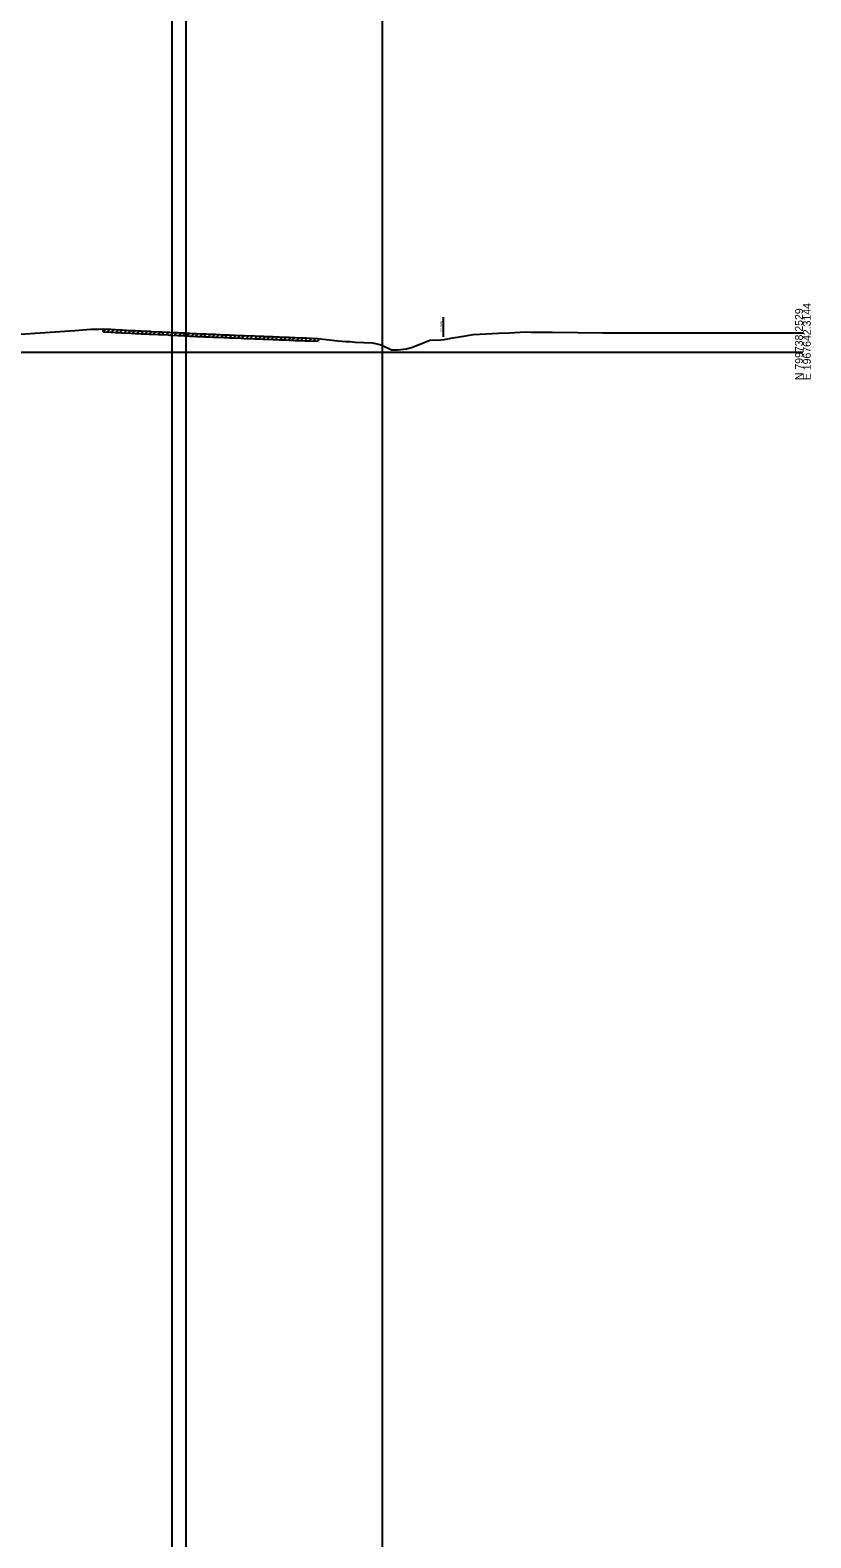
# Model space of a CAD drawing. Extents: x -119 to 6018, y -82 to 34226.
# Drawn here: x 324 to 603, y 32076 to 32614 of the extents above; entities that cross this region are included whole.
import ezdxf

# ---------------------------------------------------------------- set-up
doc = ezdxf.new("R2010")
doc.units = 0
for name, color, linetype in [('RD_GPK_XS_Cell', 7, 'Continuous'), ('RD_Sketch1', 7, 'Continuous'), ('RD_XS_ExGround', 7, 'Continuous'), ('RD_XS_ExPaveRet', 7, 'Continuous'), ('RD_XS_ExRW', 7, 'Continuous')]:
    doc.layers.add(name, color=color, linetype=linetype)

msp = doc.modelspace()

# ---------------------------------------------------------------- linework, layer by layer
at = {"layer": 'RD_GPK_XS_Cell'}
msp.add_line((300, 32499), (600, 32499), dxfattribs=at)
at = {"layer": 'RD_Sketch1'}
for p, q in [((375, -82), (375, 34226.15)), ((380, -82), (380, 34226.15)), ((450, -82), (450, 34226.15))]:
    msp.add_line(p, q, dxfattribs=at)
at = {"layer": 'RD_XS_ExGround'}
msp.add_lwpolyline([(319.1, 32505.25), (340.25, 32506.72), (345.99, 32507.12), (346.32, 32507.13), (348.98, 32507.22), (350.35, 32507.26), (353.15, 32507.14), (354.76, 32507.04), (356.69, 32506.93), (357.06, 32506.91), (360.22, 32506.74), (361.85, 32506.66), (363.39, 32506.58), (363.89, 32506.55), (365.38, 32506.48), (366.78, 32506.42), (367.16, 32506.4), (367.57, 32506.38), (370.17, 32506.27), (370.7, 32506.25), (371.27, 32506.22), (373.56, 32506.12), (374.23, 32506.08), (374.96, 32506.04), (376.97, 32505.94), (378.64, 32505.86), (379.52, 32505.81), (380.35, 32505.77), (381.31, 32505.73), (382.34, 32505.68), (383.73, 32505.61), (386.02, 32505.51), (386.59, 32505.49), (387.11, 32505.46), (388.36, 32505.41), (389.71, 32505.36), (390.51, 32505.33), (393.4, 32505.2), (393.92, 32505.18), (395.44, 32505.11), (397.31, 32505.04), (399.61, 32504.94), (400.79, 32504.89), (404.48, 32504.75), (406.07, 32504.69), (407.53, 32504.64), (408.15, 32504.61), (410.87, 32504.51), (411.85, 32504.46), (413.13, 32504.41), (414.34, 32504.36), (414.92, 32504.34), (415.55, 32504.32), (416.7, 32504.27), (417.74, 32504.23), (418.85, 32504.19), (420.86, 32504.13), (421.42, 32504.11), (422.3, 32504.07), (422.94, 32504.04), (423.63, 32504.01), (424.53, 32503.98), (427.04, 32503.88), (427.14, 32503.9), (428.97, 32503.66), (434.15, 32503.03), (437, 32502.82), (437.77, 32502.77), (438.38, 32502.72), (440.29, 32502.58), (446.46, 32502.28), (449.51, 32501.55), (453.21, 32499.82), (455.35, 32499.75), (458.65, 32500.12), (460.73, 32500.79), (466.87, 32503.3), (470.86, 32503.31), (472.01, 32503.51), (472.65, 32503.62), (473.97, 32503.85), (475.03, 32504.04), (477.54, 32504.47), (478.24, 32504.6), (478.99, 32504.73), (480.97, 32505.07), (482.4, 32505.32), (491.45, 32505.74), (495.38, 32505.92), (501.08, 32506.17), (503.09, 32506.15), (508.44, 32506.13), (510.65, 32506.07), (528.62, 32505.85), (544.18, 32505.92), (600, 32505.84)], dxfattribs=at)
at = {"layer": 'RD_XS_ExPaveRet'}
for p, q in [((350.35, 32506.26), (350.35, 32507.26)), ((350.35, 32506.26), (351.31, 32507.22)), ((350.35, 32506.26), (353.15, 32506.14)), ((351.85, 32506.2), (352.81, 32507.15)), ((353.15, 32506.14), (354.76, 32506.04)), ((353.35, 32506.12), (354.3, 32507.06)), ((354.76, 32506.04), (356.69, 32505.93)), ((354.85, 32506.03), (355.8, 32506.98)), ((356.35, 32505.95), (357.3, 32506.9)), ((356.69, 32505.93), (357.06, 32505.91)), ((357.06, 32505.91), (360.22, 32505.74)), ((357.85, 32505.87), (358.8, 32506.81)), ((359.35, 32505.78), (360.3, 32506.73)), ((360.85, 32505.7), (361.81, 32506.66)), ((362.35, 32505.63), (363.31, 32506.58)), ((363.85, 32505.56), (364.81, 32506.51)), ((365.35, 32505.48), (366.31, 32506.44)), ((366.85, 32505.41), (367.81, 32506.37)), ((368.35, 32505.35), (369.31, 32506.31)), ((369.85, 32505.29), (370.81, 32506.24)), ((371.35, 32505.22), (372.31, 32506.17)), ((372.85, 32505.15), (373.81, 32506.1)), ((374.35, 32505.07), (375.31, 32506.03)), ((375.85, 32505), (376.81, 32505.95)), ((377.35, 32504.92), (378.31, 32505.87)), ((378.85, 32504.85), (379.81, 32505.8)), ((360.22, 32505.74), (361.85, 32505.66)), ((361.85, 32505.66), (363.39, 32505.58)), ((363.39, 32505.58), (363.89, 32505.55)), ((363.89, 32505.55), (365.38, 32505.48)), ((365.38, 32505.48), (366.78, 32505.42)), ((366.78, 32505.42), (367.16, 32505.4)), ((367.16, 32505.4), (367.57, 32505.38)), ((367.57, 32505.38), (370.17, 32505.27)), ((370.17, 32505.27), (370.7, 32505.25)), ((370.7, 32505.25), (371.27, 32505.22)), ((371.27, 32505.22), (373.56, 32505.12)), ((373.56, 32505.12), (374.23, 32505.08)), ((374.23, 32505.08), (374.96, 32505.04)), ((374.96, 32505.04), (376.97, 32504.94)), ((376.97, 32504.94), (378.64, 32504.86)), ((378.64, 32504.86), (379.52, 32504.81)), ((379.52, 32504.81), (380.35, 32504.77)), ((380.35, 32504.77), (381.31, 32505.73)), ((380.35, 32504.77), (381.31, 32504.73)), ((381.31, 32504.73), (382.34, 32504.68)), ((381.85, 32504.7), (382.81, 32505.66)), ((382.34, 32504.68), (383.73, 32504.61)), ((383.35, 32504.63), (384.31, 32505.59)), ((383.73, 32504.61), (386.02, 32504.51)), ((384.85, 32504.56), (385.81, 32505.52)), ((386.02, 32504.51), (386.59, 32504.49)), ((386.35, 32504.5), (387.31, 32505.45)), ((386.59, 32504.49), (387.11, 32504.46)), ((387.11, 32504.46), (388.36, 32504.41)), ((387.85, 32504.43), (388.82, 32505.4)), ((388.36, 32504.41), (389.71, 32504.36)), ((389.35, 32504.38), (390.32, 32505.34)), ((389.71, 32504.36), (390.51, 32504.33)), ((390.51, 32504.33), (393.4, 32504.2)), ((390.85, 32504.32), (391.81, 32505.27)), ((392.35, 32504.25), (393.31, 32505.21)), ((393.4, 32504.2), (393.92, 32504.18)), ((393.85, 32504.18), (394.81, 32505.14)), ((393.92, 32504.18), (395.44, 32504.11)), ((395.35, 32504.12), (396.31, 32505.08)), ((395.44, 32504.11), (397.31, 32504.04)), ((396.85, 32504.06), (397.81, 32505.01)), ((397.31, 32504.04), (399.61, 32503.94)), ((398.35, 32503.99), (399.31, 32504.95)), ((399.61, 32503.94), (400.79, 32503.89)), ((399.85, 32503.93), (400.81, 32504.89)), ((400.79, 32503.89), (404.48, 32503.75)), ((401.35, 32503.87), (402.32, 32504.83)), ((402.85, 32503.81), (403.82, 32504.77)), ((404.35, 32503.75), (405.32, 32504.72)), ((404.48, 32503.75), (406.07, 32503.69)), ((405.85, 32503.7), (406.82, 32504.66)), ((406.07, 32503.69), (407.53, 32503.64)), ((407.35, 32503.64), (408.32, 32504.61)), ((407.53, 32503.64), (408.15, 32503.61)), ((408.15, 32503.61), (410.87, 32503.51)), ((408.85, 32503.59), (409.82, 32504.55)), ((410.35, 32503.53), (411.32, 32504.49)), ((410.87, 32503.51), (411.85, 32503.46)), ((411.85, 32503.46), (412.81, 32504.42)), ((411.85, 32503.46), (413.13, 32503.41)), ((413.13, 32503.41), (414.34, 32503.36)), ((413.35, 32503.4), (414.32, 32504.36)), ((414.34, 32503.36), (414.92, 32503.34)), ((414.85, 32503.34), (415.82, 32504.3)), ((414.92, 32503.34), (415.55, 32503.32)), ((415.55, 32503.32), (416.7, 32503.27)), ((416.35, 32503.28), (417.32, 32504.24)), ((416.7, 32503.27), (417.74, 32503.23)), ((417.74, 32503.23), (418.85, 32503.19)), ((417.85, 32503.22), (418.82, 32504.19)), ((418.85, 32503.19), (420.86, 32503.13)), ((419.35, 32503.18), (420.32, 32504.14)), ((420.85, 32503.13), (421.82, 32504.09)), ((420.86, 32503.13), (421.42, 32503.11)), ((421.42, 32503.11), (422.3, 32503.07)), ((422.3, 32503.07), (422.94, 32503.04)), ((422.35, 32503.07), (423.32, 32504.03)), ((422.94, 32503.04), (423.63, 32503.01)), ((423.63, 32503.01), (424.53, 32502.98)), ((423.85, 32503), (424.82, 32503.97)), ((424.53, 32502.98), (427.04, 32502.88)), ((425.35, 32502.95), (426.32, 32503.91)), ((427.04, 32503.88), (427.04, 32502.88))]:
    msp.add_line(p, q, dxfattribs=at)
at = {"layer": 'RD_XS_ExRW'}
msp.add_line((471.75, 32504.47), (471.75, 32511.47), dxfattribs=at)

# ---------------------------------------------------------------- texts
at = {"layer": 'RD_GPK_XS_Cell'}
for s, p in [('N 799738.2529', (600, 32489)), ('E 1967642.3144', (602.8, 32489))]:
    msp.add_text(s, height=2.8, rotation=90, dxfattribs=at).set_placement(p)
at = {"layer": 'RD_XS_ExRW'}
msp.add_text('EX. R/W ', height=0.75, rotation=90, dxfattribs=at).set_placement((471.43, 32506.14))

doc.saveas('drawing.dxf')
